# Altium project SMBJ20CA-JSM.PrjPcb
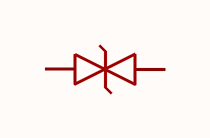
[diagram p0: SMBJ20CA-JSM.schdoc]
1 sheet, 1 parts. Net scope: global (net labels, ports and power ports of the same name join across sheets).

## Sheet SMBJ20CA-JSM.schdoc
size 127 x 101 mm

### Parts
D?  smbj20ca-jsm  [SMB_L4.8-W3.9-LS5.6-BI]  (value not drawn)

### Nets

Not connected (* = marked no-connect by the designer): D? 1 2

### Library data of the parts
D? = smbj20ca-jsm: 极性:双向;反向截止电压(Vrwm):20V;钳位电压:32.4V;峰值脉冲电流(Ipp):18.6A;峰值脉冲功率(Ppp):600W;击穿电压(VBR):24.5V;; Manufacturer: JSMSEMI(杰盛微); AddInBom: yes; Polarity: 双向; Reverse Stand-Off Voltage (Vrwm): 20V; Clamping Voltage: 32.4V; Peak Pulse Current (Ipp): 18.6A; Peak Pulse Power Dissipation (Ppp): 600W; Voltage - Breakdown: 24.5V; Reverse Leakage Current (Ir): 1uA; Number of Channels: 单路; Type: TVS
